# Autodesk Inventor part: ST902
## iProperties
Created: 2006-02
Part Number: ST902
Material: -
Description: Vis CHcx, ISO 4762 - M6 x 40
Document SubType Name: Modeling
Standard: ISO 4762
Designer: Gilles GLEMAREC
Standard Revision: Quatrième édition 2004-03-01
Standards Organization: ISO
Language: fr-FR
Size Designation: M6 x 40
Categories: <MemberInstance><Categories><Category DisplayName="Visserie" InternalName="e4da775c-781d-43d5-af7c-5136215cf5a6" Mnemonic="FSTN"><Category DisplayName="Vis" Int
Stock Number: ST902
Author: Gilles GLEMAREC
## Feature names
1. Corps [Revolution]
2. Rainure [Extrusion]
3. Congé1 [Fillet]
4. Chanfrein1 [Chamfer]
